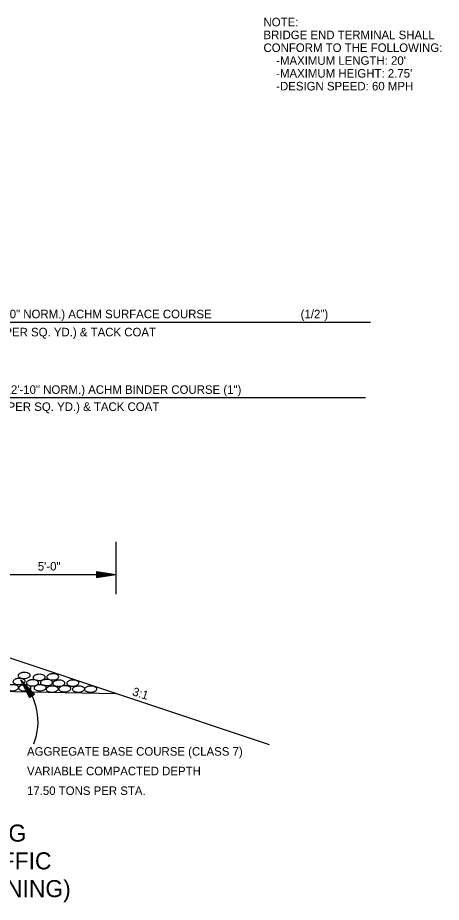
# Model space of a CAD drawing. Extents: x 634177 to 635904, y 289936 to 290970.
# Drawn here: x 635683.7 to 635713.4, y 290818.2 to 290880.3 of the extents above; entities that cross this region are included whole.
import ezdxf

# ---------------------------------------------------------------- set-up
doc = ezdxf.new("R2010")
doc.units = 0
doc.layers.add('Default', color=7, linetype='Continuous')

msp = doc.modelspace()

# ---------------------------------------------------------------- linework, layer by layer
at = {"layer": 'Default'}
for p, q in [((635708.459, 290858.879), (635677.234, 290858.879)), ((635708.11, 290853.592), (635677.541, 290853.592)), ((635690.566, 290843.476), (635690.566, 290839.811)), ((635681.573, 290841.181), (635690.566, 290841.181)), ((635689.198, 290841.385), (635690.566, 290841.181)), ((635689.198, 290841.385), (635689.198, 290840.975)), ((635689.198, 290841.352), (635690.337, 290841.181)), ((635689.198, 290841.316), (635690.1, 290841.181)), ((635689.198, 290841.283), (635689.871, 290841.181)), ((635689.198, 290841.246), (635689.64, 290841.181)), ((635689.198, 290841.213), (635689.411, 290841.181)), ((635689.198, 290840.975), (635690.566, 290841.181)), ((635689.198, 290841.112), (635689.64, 290841.181)), ((635689.198, 290841.043), (635690.1, 290841.181)), ((635689.198, 290841.009), (635690.337, 290841.181)), ((635689.198, 290841.079), (635689.871, 290841.181)), ((635689.198, 290841.148), (635689.411, 290841.181)), ((635681.573, 290835.834), (635701.326, 290829.249)), ((635651.936, 290833.608), (635690.566, 290832.836)), ((635684.507, 290832.543), (635683.895, 290833.785)), ((635684.845, 290832.78), (635683.895, 290833.785)), ((635684.535, 290832.561), (635684.027, 290833.598)), ((635684.817, 290832.756), (635684.027, 290833.598)), ((635684.788, 290832.739), (635684.161, 290833.403)), ((635684.565, 290832.582), (635684.161, 290833.403)), ((635684.594, 290832.602), (635684.29, 290833.216)), ((635684.759, 290832.717), (635684.29, 290833.216)), ((635684.731, 290832.699), (635684.424, 290833.026)), ((635684.622, 290832.624), (635684.424, 290833.026)), ((635684.507, 290832.543), (635684.845, 290832.78)), ((635684.702, 290832.678), (635684.554, 290832.84)), ((635684.65, 290832.641), (635684.554, 290832.84))]:
    msp.add_line(p, q, dxfattribs=at)
msp.add_arc((635680.911, 290830.854), 4.183, 337.99323, 44.48216, dxfattribs=at)
for points in [[(635684.117, 290834.303), (635684.27, 290834.302), (635684.452, 290834.238), (635684.541, 290834.155), (635684.553, 290834.101), (635684.507, 290834.009), (635684.455, 290833.97), (635684.355, 290833.918), (635684.209, 290833.884), (635684.133, 290833.876), (635684.022, 290833.887), (635683.896, 290833.908), (635683.801, 290833.945), (635683.713, 290834.018), (635683.698, 290834.076), (635683.724, 290834.158), (635683.794, 290834.211), (635683.858, 290834.253), (635683.96, 290834.288), (635684.023, 290834.302), (635684.117, 290834.303)], [(635685.166, 290834.173), (635685.317, 290834.172), (635685.499, 290834.108), (635685.591, 290834.022), (635685.605, 290833.972), (635685.555, 290833.879), (635685.503, 290833.837), (635685.406, 290833.788), (635685.255, 290833.751), (635685.181, 290833.746), (635685.068, 290833.754), (635684.946, 290833.776), (635684.851, 290833.815), (635684.762, 290833.885), (635684.748, 290833.947), (635684.775, 290834.025), (635684.843, 290834.081), (635684.909, 290834.125), (635685.007, 290834.158), (635685.069, 290834.172), (635685.166, 290834.173)], [(635686.123, 290834.204), (635686.274, 290834.202), (635686.458, 290834.14), (635686.545, 290834.054), (635686.559, 290834.004), (635686.511, 290833.909), (635686.46, 290833.869), (635686.36, 290833.82), (635686.213, 290833.783), (635686.137, 290833.778), (635686.026, 290833.786), (635685.902, 290833.808), (635685.805, 290833.847), (635685.716, 290833.917), (635685.704, 290833.975), (635685.732, 290834.057), (635685.801, 290834.112), (635685.863, 290834.155), (635685.964, 290834.19), (635686.028, 290834.202), (635686.123, 290834.204)], [(635683.288, 290833.443), (635683.439, 290833.442), (635683.621, 290833.378), (635683.713, 290833.292), (635683.727, 290833.242), (635683.677, 290833.149), (635683.624, 290833.107), (635683.528, 290833.058), (635683.377, 290833.021), (635683.303, 290833.016), (635683.19, 290833.024), (635683.068, 290833.046), (635682.973, 290833.085), (635682.884, 290833.155), (635682.87, 290833.217), (635682.897, 290833.295), (635682.965, 290833.351), (635683.031, 290833.395), (635683.129, 290833.428), (635683.191, 290833.442), (635683.288, 290833.443)], [(635683.755, 290833.883), (635683.903, 290833.882), (635684.087, 290833.819), (635684.174, 290833.732), (635684.19, 290833.682), (635684.143, 290833.589), (635684.089, 290833.548), (635683.99, 290833.5), (635683.844, 290833.462), (635683.766, 290833.458), (635683.657, 290833.464), (635683.532, 290833.484), (635683.437, 290833.525), (635683.348, 290833.595), (635683.334, 290833.654), (635683.362, 290833.737), (635683.431, 290833.793), (635683.492, 290833.836), (635683.595, 290833.866), (635683.659, 290833.882), (635683.755, 290833.883)], [(635684.159, 290833.435), (635684.31, 290833.433), (635684.492, 290833.369), (635684.584, 290833.283), (635684.598, 290833.233), (635684.548, 290833.14), (635684.495, 290833.098), (635684.399, 290833.05), (635684.247, 290833.012), (635684.174, 290833.008), (635684.06, 290833.015), (635683.939, 290833.037), (635683.844, 290833.076), (635683.755, 290833.146), (635683.741, 290833.209), (635683.768, 290833.286), (635683.836, 290833.343), (635683.902, 290833.386), (635684, 290833.419), (635684.062, 290833.433), (635684.159, 290833.435)], [(635684.699, 290833.784), (635684.85, 290833.783), (635685.032, 290833.719), (635685.124, 290833.633), (635685.138, 290833.583), (635685.088, 290833.49), (635685.036, 290833.448), (635684.939, 290833.4), (635684.788, 290833.362), (635684.715, 290833.357), (635684.601, 290833.365), (635684.479, 290833.387), (635684.384, 290833.426), (635684.295, 290833.496), (635684.281, 290833.558), (635684.308, 290833.636), (635684.376, 290833.692), (635684.442, 290833.736), (635684.54, 290833.769), (635684.602, 290833.783), (635684.699, 290833.784)], [(635685.234, 290833.443), (635685.385, 290833.442), (635685.568, 290833.378), (635685.66, 290833.292), (635685.674, 290833.242), (635685.624, 290833.149), (635685.571, 290833.107), (635685.474, 290833.058), (635685.323, 290833.021), (635685.25, 290833.016), (635685.136, 290833.024), (635685.014, 290833.046), (635684.919, 290833.085), (635684.831, 290833.155), (635684.817, 290833.217), (635684.843, 290833.295), (635684.912, 290833.351), (635684.977, 290833.395), (635685.075, 290833.428), (635685.138, 290833.442), (635685.234, 290833.443)], [(635685.681, 290833.806), (635685.832, 290833.804), (635686.016, 290833.742), (635686.104, 290833.654), (635686.116, 290833.605), (635686.071, 290833.513), (635686.018, 290833.469), (635685.918, 290833.422), (635685.77, 290833.386), (635685.697, 290833.379), (635685.583, 290833.388), (635685.458, 290833.408), (635685.366, 290833.447), (635685.275, 290833.517), (635685.262, 290833.577), (635685.29, 290833.659), (635685.357, 290833.714), (635685.421, 290833.759), (635685.522, 290833.79), (635685.586, 290833.804), (635685.681, 290833.806)], [(635686.548, 290833.755), (635686.697, 290833.754), (635686.878, 290833.691), (635686.969, 290833.604), (635686.984, 290833.556), (635686.936, 290833.462), (635686.881, 290833.419), (635686.783, 290833.374), (635686.635, 290833.338), (635686.56, 290833.33), (635686.451, 290833.339), (635686.325, 290833.36), (635686.231, 290833.397), (635686.14, 290833.467), (635686.127, 290833.528), (635686.155, 290833.61), (635686.224, 290833.665), (635686.286, 290833.709), (635686.387, 290833.738), (635686.453, 290833.754), (635686.548, 290833.755)], [(635687.532, 290833.767), (635687.683, 290833.766), (635687.867, 290833.705), (635687.956, 290833.618), (635687.97, 290833.569), (635687.921, 290833.473), (635687.868, 290833.432), (635687.769, 290833.387), (635687.621, 290833.35), (635687.547, 290833.343), (635687.434, 290833.351), (635687.31, 290833.372), (635687.217, 290833.41), (635687.125, 290833.482), (635687.114, 290833.54), (635687.141, 290833.621), (635687.208, 290833.677), (635687.273, 290833.721), (635687.373, 290833.753), (635687.437, 290833.766), (635687.532, 290833.767)], [(635686.086, 290833.347), (635686.237, 290833.346), (635686.42, 290833.282), (635686.511, 290833.196), (635686.525, 290833.146), (635686.476, 290833.053), (635686.423, 290833.011), (635686.326, 290832.962), (635686.175, 290832.925), (635686.102, 290832.92), (635685.988, 290832.928), (635685.866, 290832.95), (635685.771, 290832.989), (635685.682, 290833.059), (635685.668, 290833.121), (635685.695, 290833.199), (635685.763, 290833.255), (635685.829, 290833.299), (635685.927, 290833.332), (635685.989, 290833.346), (635686.086, 290833.347)], [(635686.972, 290833.371), (635687.123, 290833.369), (635687.304, 290833.307), (635687.396, 290833.219), (635687.407, 290833.171), (635687.361, 290833.076), (635687.308, 290833.036), (635687.21, 290832.987), (635687.061, 290832.95), (635686.986, 290832.944), (635686.874, 290832.955), (635686.751, 290832.975), (635686.654, 290833.012), (635686.567, 290833.085), (635686.551, 290833.143), (635686.578, 290833.224), (635686.648, 290833.28), (635686.712, 290833.322), (635686.814, 290833.355), (635686.875, 290833.369), (635686.972, 290833.371)], [(635687.936, 290833.347), (635688.086, 290833.346), (635688.268, 290833.282), (635688.36, 290833.198), (635688.373, 290833.145), (635688.324, 290833.053), (635688.27, 290833.011), (635688.175, 290832.961), (635688.023, 290832.93), (635687.95, 290832.919), (635687.836, 290832.931), (635687.715, 290832.951), (635687.621, 290832.99), (635687.531, 290833.059), (635687.515, 290833.12), (635687.544, 290833.201), (635687.612, 290833.257), (635687.678, 290833.299), (635687.776, 290833.33), (635687.838, 290833.346), (635687.936, 290833.347)], [(635688.785, 290833.341), (635688.938, 290833.34), (635689.12, 290833.276), (635689.209, 290833.193), (635689.221, 290833.139), (635689.175, 290833.047), (635689.123, 290833.008), (635689.023, 290832.956), (635688.877, 290832.922), (635688.801, 290832.914), (635688.69, 290832.925), (635688.564, 290832.946), (635688.469, 290832.983), (635688.381, 290833.056), (635688.366, 290833.114), (635688.392, 290833.196), (635688.462, 290833.249), (635688.526, 290833.291), (635688.628, 290833.326), (635688.691, 290833.34), (635688.785, 290833.341)]]:
    msp.add_spline(points, degree=3, dxfattribs=at)

# ---------------------------------------------------------------- texts
for s, height, p in [('NOTE:', 0.6, (635700.938, 290879.675)), ('BRIDGE END TERMINAL SHALL', 0.6, (635700.938, 290878.775)), ('CONFORM TO THE FOLLOWING:', 0.6, (635700.938, 290877.875)), ("    -MAXIMUM LENGTH: 20' ", 0.6, (635700.938, 290876.975)), ("    -MAXIMUM HEIGHT: 2.75' ", 0.6, (635700.938, 290876.075)), ('    -DESIGN SPEED: 60 MPH', 0.6, (635700.938, 290875.175)), ('VAR. (12\'-10" NORM.) ACHM SURFACE COURSE', 0.6, (635678.983, 290859.176)), ('(1/2")', 0.6, (635703.551, 290859.176)), ('(220 LBS. PER SQ. YD.) & TACK COAT', 0.6, (635678.938, 290857.906)), ('VAR. (12\'-10" NORM.) ACHM BINDER COURSE (1")', 0.6, (635680.382, 290853.869)), ('(440 LBS. PER SQ. YD.) & TACK COAT', 0.6, (635679.166, 290852.669)), ('5\'-0"', 0.6, (635685.078, 290841.461)), ('AGGREGATE BASE COURSE (CLASS 7)', 0.6, (635684.319, 290828.461)), ('VARIABLE COMPACTED DEPTH', 0.6, (635684.319, 290827.082)), ('17.50 TONS PER STA.', 0.6, (635684.319, 290825.703)), ('TEMPORARY WIDENING ', 1.2, (635665.456, 290822.426)), ('FOR MAINTENANCE OF TRAFFIC', 1.2, (635660.631, 290820.476)), ('(SHOWN IN DIRECTION OF STATIONING)', 1.2, (635655.927, 290818.526))]:
    msp.add_text(s, height=height, dxfattribs=at).set_placement(p)
msp.add_text('3:1', height=0.6, rotation=342.71846, dxfattribs=at).set_placement((635691.679, 290832.71))

doc.saveas('drawing.dxf')
